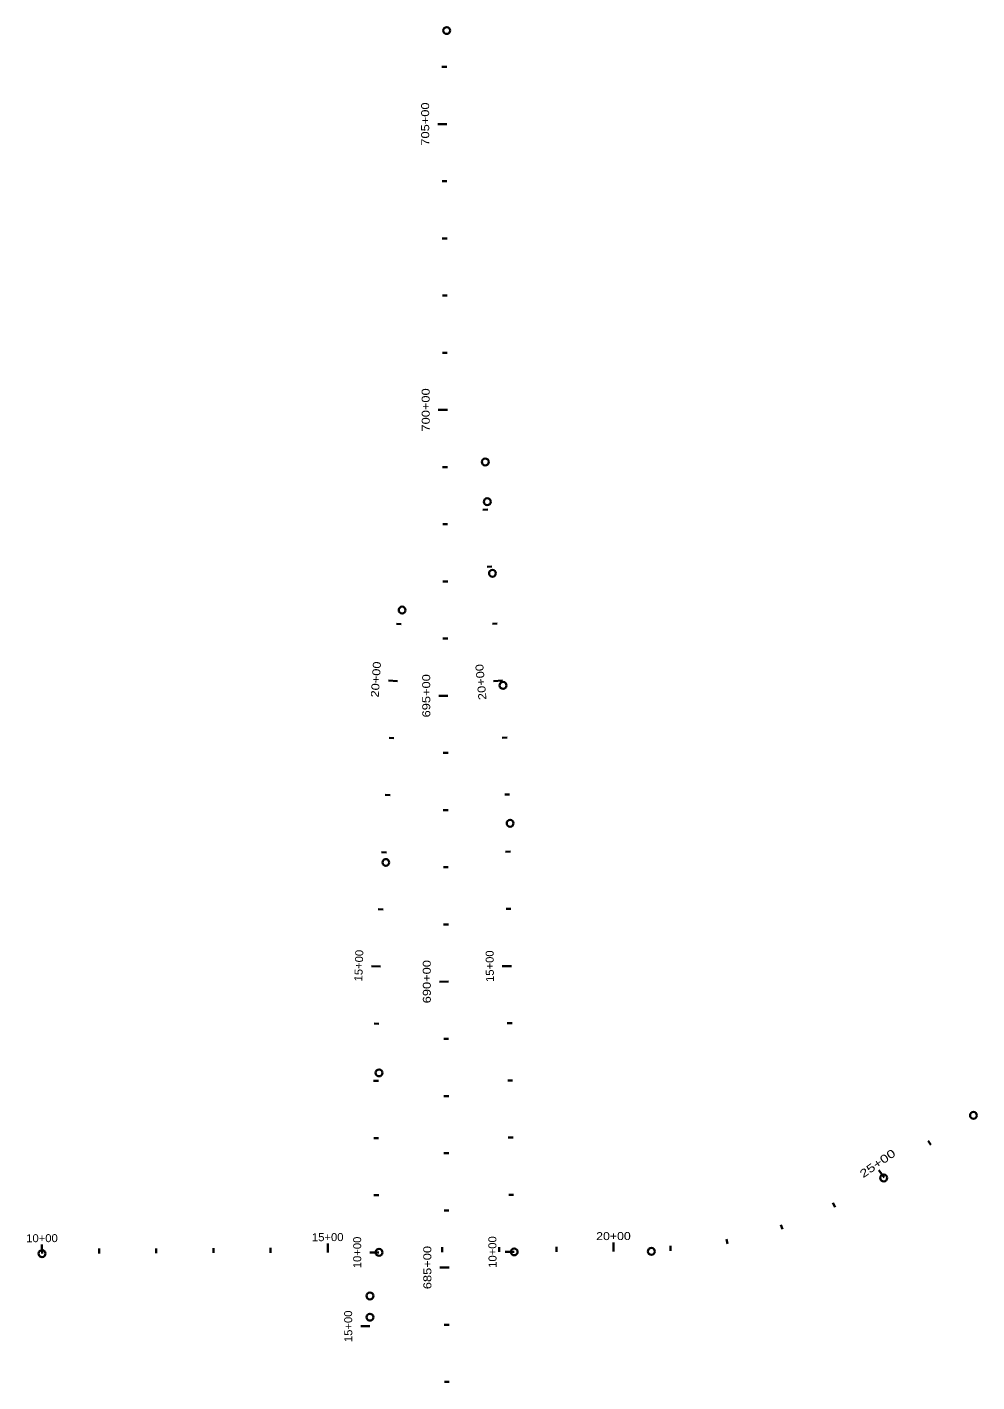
# Model space of a CAD drawing. Extents: x 2357892 to 2370172, y 6966790 to 6985499.
# Drawn here: x 2363683 to 2365345, y 6969127 to 6971496 of the extents above; entities that cross this region are included whole.
import ezdxf
from ezdxf.enums import TextEntityAlignment as Align

# ---------------------------------------------------------------- set-up
doc = ezdxf.new("R2010")
doc.units = 0
doc.header["$LTSCALE"] = 5.6
doc.layers.add('28', color=7, linetype='Continuous', lineweight=35)

msp = doc.modelspace()

# ---------------------------------------------------------------- linework, layer by layer
at = {"layer": '28'}
for p, q in [((2364417.228, 6971426.541), (2364408.728, 6971426.525)), ((2364417.418, 6971326.541), (2364401.418, 6971326.51)), ((2364417.608, 6971226.541), (2364409.108, 6971226.525)), ((2364417.798, 6971126.541), (2364409.298, 6971126.525)), ((2364417.988, 6971026.541), (2364409.488, 6971026.525)), ((2364418.178, 6970926.542), (2364409.678, 6970926.525)), ((2364418.368, 6970826.542), (2364402.368, 6970826.511)), ((2364418.558, 6970726.542), (2364410.058, 6970726.526)), ((2364488.906, 6970652.323), (2364480.419, 6970651.858)), ((2364418.748, 6970626.542), (2364410.248, 6970626.526)), ((2364496.116, 6970552.588), (2364487.651, 6970551.827)), ((2364418.938, 6970526.542), (2364410.438, 6970526.526)), ((2364337.52, 6970451.9), (2364329.038, 6970452.447)), ((2364505.455, 6970453.025), (2364496.992, 6970452.229)), ((2364419.128, 6970426.542), (2364410.628, 6970426.526)), ((2364331.08, 6970352.107), (2364315.113, 6970353.138)), ((2364514.817, 6970353.464), (2364498.888, 6970351.966)), ((2364419.319, 6970326.543), (2364403.319, 6970326.512)), ((2364324.64, 6970252.315), (2364316.158, 6970252.862)), ((2364522.734, 6970253.783), (2364514.251, 6970253.257)), ((2364419.509, 6970226.543), (2364411.009, 6970226.527)), ((2364318.2, 6970152.523), (2364309.718, 6970153.07)), ((2364527.181, 6970153.887), (2364518.684, 6970153.657)), ((2364419.699, 6970126.543), (2364411.199, 6970126.527)), ((2364311.76, 6970052.73), (2364303.278, 6970053.278)), ((2364528.57, 6970053.898), (2364520.071, 6970053.818)), ((2364419.889, 6970026.543), (2364411.389, 6970026.527)), ((2364305.699, 6969952.915), (2364297.211, 6969953.365)), ((2364529.518, 6969953.903), (2364521.019, 6969953.822)), ((2364420.079, 6969926.543), (2364411.579, 6969926.527)), ((2364301.279, 6969853.014), (2364285.289, 6969853.581)), ((2364530.466, 6969853.907), (2364514.467, 6969853.756)), ((2364420.269, 6969826.544), (2364404.269, 6969826.513)), ((2364298.604, 6969753.051), (2364290.105, 6969753.204)), ((2364531.414, 6969753.912), (2364522.915, 6969753.831)), ((2364420.459, 6969726.544), (2364411.959, 6969726.528)), ((2364297.673, 6969653.056), (2364289.173, 6969653.061)), ((2364532.362, 6969653.916), (2364523.863, 6969653.836)), ((2364420.649, 6969626.544), (2364412.149, 6969626.528)), ((2364297.932, 6969553.057), (2364289.432, 6969553.032)), ((2364533.31, 6969553.921), (2364524.811, 6969553.84)), ((2365264.545, 6969540.9), (2365259.687, 6969547.875)), ((2364420.839, 6969526.544), (2364412.339, 6969526.528)), ((2365182.49, 6969483.743), (2365173.344, 6969496.872)), ((2364298.227, 6969453.057), (2364289.727, 6969453.032)), ((2364534.258, 6969453.925), (2364525.759, 6969453.845)), ((2365096.772, 6969432.399), (2365092.923, 6969439.978)), ((2364421.029, 6969426.544), (2364412.529, 6969426.528)), ((2365004.741, 6969393.488), (2365001.985, 6969401.529)), ((2364209.017, 6969352.732), (2364208.958, 6969368.732)), ((2364709.013, 6969354.574), (2364708.954, 6969370.574)), ((2364908.189, 6969367.768), (2364906.58, 6969376.114)), ((2363709.02, 6969350.89), (2363708.961, 6969366.89)), ((2363809.019, 6969351.258), (2363808.988, 6969359.758)), ((2363909.019, 6969351.627), (2363908.987, 6969360.127)), ((2364009.018, 6969351.995), (2364008.987, 6969360.495)), ((2364109.017, 6969352.364), (2364108.986, 6969360.864)), ((2364298.521, 6969353.058), (2364282.521, 6969353.011)), ((2364409.015, 6969353.469), (2364408.984, 6969361.969)), ((2364509.015, 6969353.837), (2364508.983, 6969362.337)), ((2364535.206, 6969353.93), (2364519.207, 6969353.778)), ((2364609.014, 6969354.206), (2364608.983, 6969362.706)), ((2364808.997, 6969355.739), (2364808.565, 6969364.228)), ((2364421.219, 6969326.544), (2364405.219, 6969326.514)), ((2364421.409, 6969226.545), (2364412.909, 6969226.529)), ((2364282.83, 6969224.003), (2364266.83, 6969223.871)), ((2364421.599, 6969126.545), (2364413.099, 6969126.529))]:
    msp.add_line(p, q, dxfattribs=at)
for centre in [(2364417.107, 6971490.047), (2364484.715, 6970735.499), (2364488.193, 6970665.934), (2364497.202, 6970540.778), (2364339.101, 6970476.397), (2364339.101, 6970476.397), (2364515.644, 6970344.67), (2364528.099, 6970103.612), (2364310.616, 6970035), (2364310.616, 6970035), (2364298.722, 6969667.003), (2364298.722, 6969667.003), (2365338.91, 6969592.7), (2365181.865, 6969483.308), (2363709.02, 6969350.89), (2364298.668, 6969353.062), (2364298.668, 6969353.062), (2364535.206, 6969353.93), (2364775.243, 6969354.818), (2364282.765, 6969276.848), (2364282.765, 6969239.722)]:
    msp.add_circle(centre, 6, dxfattribs=at)

# ---------------------------------------------------------------- texts
for s, rotation, width, p in [('705+00', 90.109, 1.2, (2364386.418, 6971326.495)), ('700+00', 90.109, 1.2, (2364387.368, 6970826.496)), ('20+00', 86.308, 1.2, (2364300.174, 6970354.556)), ('20+00', 95.372, 1.2, (2364483.892, 6970351.218)), ('695+00', 90.109, 1.2, (2364388.318, 6970326.497)), ('15+00', 87.967, 1.05, (2364270.308, 6969854.361)), ('15+00', 90.543, 1.05, (2364499.467, 6969853.68)), ('690+00', 90.109, 1.2, (2364389.269, 6969826.498)), ('25+00', 34.86, 1.35, (2365175.059, 6969502.941)), ('10+00', 0.211, 1.05, (2363708.973, 6969370.89)), ('15+00', 0.211, 1.05, (2364208.969, 6969372.732)), ('10+00', 90.169, 1.05, (2364267.521, 6969352.988)), ('10+00', 90.543, 1.05, (2364504.207, 6969353.703)), ('20+00', 0.211, 1.15, (2364708.966, 6969374.574)), ('685+00', 90.109, 1.2, (2364390.219, 6969326.5)), ('15+00', 90.472, 1.05, (2364251.83, 6969223.806))]:
    msp.add_text(s, height=14, rotation=rotation, dxfattribs=dict(at, width=width)).set_placement(p, align=Align.CENTER)

doc.saveas('drawing.dxf')
